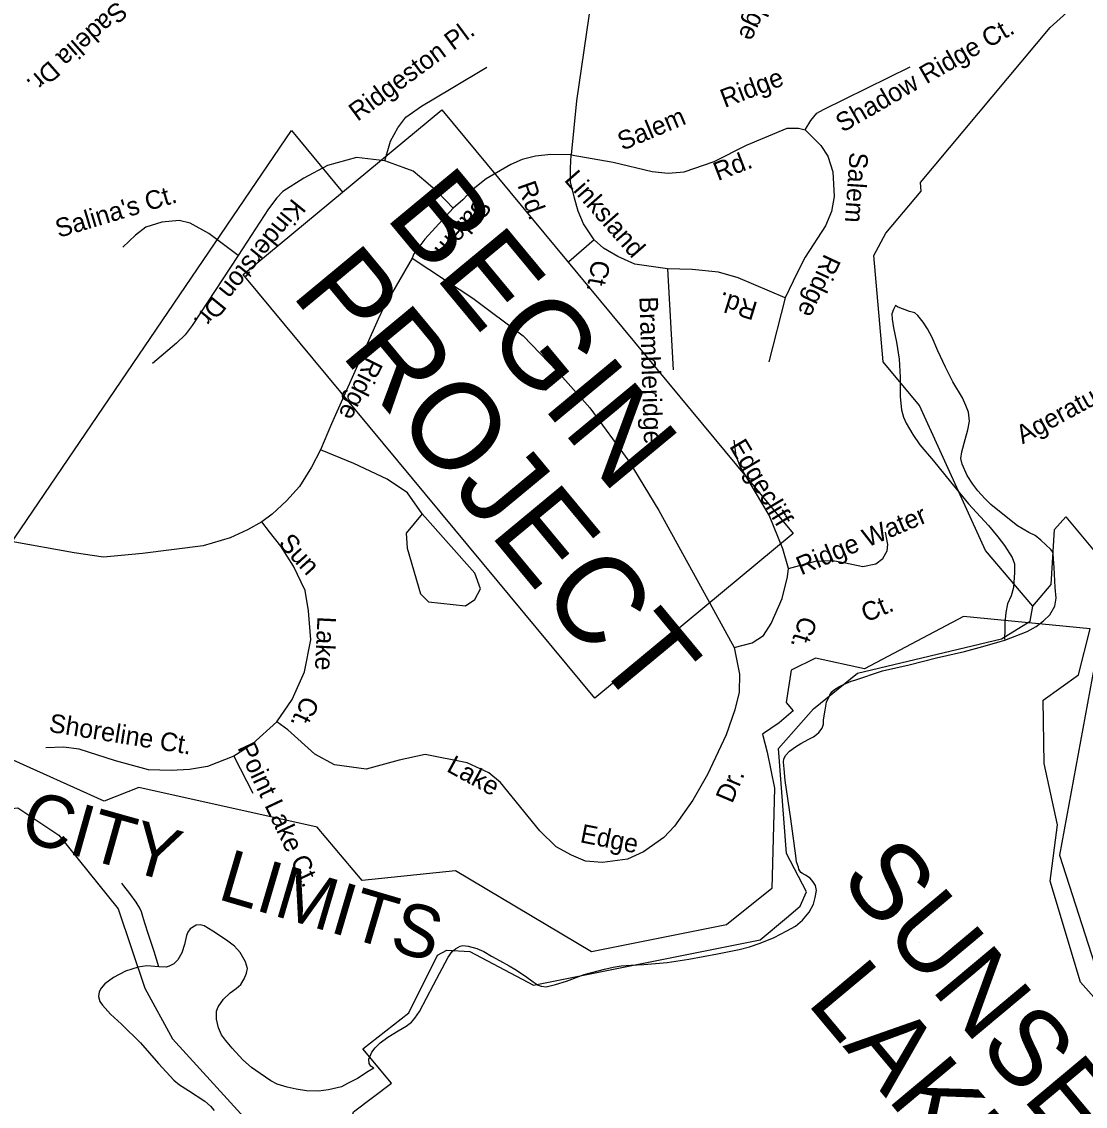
# Model space of a CAD drawing. Extents: x 2054826 to 2060231, y 685508 to 690809.
# Drawn here: x 2058702.3 to 2058824.2, y 689558.4 to 689682.8 of the extents above; entities that cross this region are included whole.
import ezdxf

# ---------------------------------------------------------------- set-up
doc = ezdxf.new("R2010")
doc.units = 0
for name, color, linetype in [('Old_Level_10', 7, 'Continuous'), ('Old_Level_19', 7, 'Continuous'), ('Old_Level_21', 7, 'Continuous'), ('Old_Level_35', 7, 'Continuous'), ('Old_Level_48', 7, 'Continuous'), ('Old_Level_49', 7, 'Continuous'), ('Old_Level_59', 7, 'Continuous'), ('Old_Level_60', 7, 'Continuous'), ('Old_Level_62', 7, 'Continuous'), ('Prop Dimension', 7, 'Continuous'), ('Prop Horizontal Alignment Station Label', 7, 'Continuous')]:
    doc.layers.add(name, color=color, linetype=linetype)

msp = doc.modelspace()

# ---------------------------------------------------------------- linework, layer by layer
at = {"layer": 'Old_Level_21'}
msp.add_line((2058805.24, 689577.2), (2058805.24, 689577.2), dxfattribs=at)
at = {"layer": 'Old_Level_35'}
for p, q in [((2058767.9, 689657.81), (2058765.02, 689655.29)), ((2058776.31, 689654.46), (2058776.97, 689642.9)), ((2058789.8, 689651.16), (2058787.92, 689643.79)), ((2058726.58, 689598.57), (2058728.76, 689594.34))]:
    msp.add_line(p, q, dxfattribs=at)
for points in [[(2058764.19, 689707.99), (2058766.14, 689702.54), (2058767.28, 689698.06), (2058767.69, 689693.65), (2058767.83, 689688.67), (2058767.56, 689685.33), (2058765.89, 689673.74), (2058765.28, 689667.56)], [(2058743.9, 689666.85), (2058744.57, 689669.11), (2058745.38, 689670.64), (2058746.33, 689671.88), (2058748.1, 689673.14), (2058751.52, 689675.15), (2058755.6, 689677.6)], [(2058792.11, 689670.42), (2058792.76, 689671.47), (2058793.46, 689672.33), (2058794.2, 689672.73), (2058804.14, 689677.65)], [(2058765.28, 689667.56), (2058770.07, 689666.7), (2058774.57, 689665.65), (2058776.4, 689665.43), (2058778.24, 689665.61), (2058781.67, 689666.78), (2058785.39, 689668.64), (2058790.03, 689670.6), (2058791.33, 689670.61), (2058792.11, 689670.42)], [(2058792.11, 689670.42), (2058793.9, 689668.63), (2058794.71, 689667.38), (2058795.29, 689665.6), (2058795.41, 689662.75), (2058795.13, 689661.05), (2058794.43, 689659.39), (2058792.1, 689655.8), (2058791.2, 689654.03), (2058789.8, 689651.16)], [(2058743.9, 689666.85), (2058740.66, 689667.25), (2058737.34, 689666.34), (2058734.61, 689664.86), (2058732.2, 689663.35), (2058731.51, 689662.61), (2058730.58, 689661.37), (2058727.07, 689656)], [(2058765.28, 689667.56), (2058762.94, 689667.6), (2058761.19, 689667.38), (2058759.65, 689667), (2058758.36, 689666.43), (2058755.53, 689664.8), (2058753.84, 689663.44), (2058752.85, 689662.39), (2058751.74, 689661.41)], [(2058767.9, 689657.81), (2058766.7, 689659.64), (2058766.06, 689661.09), (2058765.67, 689662.57), (2058765.19, 689664.43), (2058765.18, 689666.01), (2058765.28, 689667.56)], [(2058751.74, 689661.41), (2058749.97, 689663.26), (2058748.62, 689664.46), (2058747.16, 689665.67), (2058746, 689666.11), (2058743.9, 689666.85)], [(2058751.74, 689661.41), (2058748.51, 689657.86), (2058747.25, 689656.18), (2058747.03, 689655.71)], [(2058727.07, 689656), (2058723.73, 689658.51), (2058721.59, 689659.72), (2058720.32, 689660.02), (2058718.33, 689659.82), (2058716.49, 689659.25), (2058715.33, 689658.33), (2058713.87, 689656.94)], [(2058776.31, 689654.46), (2058772.58, 689654.99), (2058770.63, 689655.9), (2058768.98, 689656.85), (2058767.9, 689657.81)], [(2058727.07, 689656), (2058721.83, 689647.97), (2058721.02, 689646.9), (2058720.01, 689645.94), (2058717.25, 689643.63)], [(2058747.03, 689655.71), (2058743.8, 689650.08), (2058743.15, 689648.69), (2058737.8, 689636.68), (2058736.54, 689633.71)], [(2058747.03, 689655.71), (2058750.86, 689653.16), (2058754.01, 689651.1), (2058759.76, 689646.79), (2058763.66, 689642.75), (2058767.41, 689638.53), (2058771.89, 689632.43), (2058775.33, 689626.76), (2058780.11, 689618.07), (2058783.95, 689611.03)], [(2058789.8, 689651.16), (2058784.43, 689653.44), (2058782.15, 689654.08), (2058779.15, 689654.4), (2058776.31, 689654.46)], [(2058790.19, 689620.1), (2058789.56, 689622.35), (2058787.96, 689626.22), (2058785.68, 689630.09), (2058784.64, 689631.82), (2058784.19, 689633.03), (2058783.98, 689634.84)], [(2058736.54, 689633.71), (2058735.49, 689631.74), (2058734.12, 689629.52), (2058732.62, 689627.87), (2058731, 689626.35), (2058729.82, 689625.46)], [(2058748.19, 689626.36), (2058746.5, 689628.78), (2058744.19, 689630.34), (2058740.35, 689632.14), (2058736.54, 689633.71)], [(2058748.19, 689626.36), (2058746.36, 689624.16), (2058746.47, 689622.42), (2058748.01, 689617.2), (2058748.92, 689616.3), (2058753.15, 689615.84), (2058754.21, 689616.56), (2058754.87, 689617.77), (2058754.21, 689619.56), (2058748.19, 689626.36)], [(2058729.82, 689625.46), (2058728.17, 689624.55), (2058726.18, 689623.62), (2058723.07, 689622.72), (2058716.12, 689621.83), (2058711.64, 689621.42), (2058708.29, 689621.9), (2058701.07, 689623.22), (2058698.61, 689623.55), (2058694.9, 689623.44), (2058690.83, 689622.76), (2058682.54, 689620.63)], [(2058731.53, 689602.54), (2058733.27, 689605.08), (2058734.7, 689608.25), (2058735.43, 689611.92), (2058735.17, 689615.27), (2058734.76, 689617.59), (2058733.44, 689620.39), (2058731.98, 689622.68), (2058730.67, 689624.31), (2058729.82, 689625.46)], [(2058790.19, 689620.1), (2058793.29, 689620.94), (2058795.27, 689621.01), (2058796.72, 689620.76), (2058798.72, 689620.33), (2058800.2, 689620.66), (2058801, 689621.27), (2058801.51, 689622.15), (2058801.6, 689622.85), (2058801.33, 689624.26)], [(2058783.95, 689611.03), (2058786.04, 689611.59), (2058787.31, 689612.43), (2058788.21, 689613.8), (2058789.45, 689616.65), (2058790.07, 689619.16), (2058790.19, 689620.1)], [(2058783.95, 689611.03), (2058784.58, 689607.99), (2058784.55, 689605.93), (2058784.03, 689603.91), (2058783.03, 689601.04), (2058780.9, 689596.48), (2058779.23, 689593.53), (2058777.11, 689590.57), (2058775.89, 689589.26), (2058773.58, 689587.62), (2058771.74, 689586.76), (2058768.85, 689586.38), (2058766.9, 689586.56), (2058765.32, 689587.22), (2058763.56, 689588.18), (2058761.66, 689590.04), (2058757.15, 689595.56), (2058755.83, 689596.67), (2058753.34, 689597.81), (2058748.53, 689598.77), (2058745.54, 689598.12), (2058741.75, 689597.1), (2058738.12, 689597.58), (2058735.89, 689598.83), (2058732.77, 689601.6), (2058731.53, 689602.54)], [(2058731.53, 689602.54), (2058728.74, 689599.99), (2058727.62, 689599.22), (2058726.58, 689598.57)], [(2058726.58, 689598.57), (2058723.58, 689597.42), (2058721.51, 689597.05), (2058719.4, 689596.93), (2058716.79, 689597.01), (2058713.02, 689598.05), (2058708.86, 689599.38), (2058707.06, 689599.63), (2058705.04, 689599.53)]]:
    msp.add_lwpolyline(points, dxfattribs=at)
at = {"layer": 'Old_Level_48'}
msp.add_lwpolyline([(2058827.31, 689568.59), (2058823.67, 689572.68), (2058820.19, 689584.27), (2058821.02, 689590.71), (2058819.51, 689597.74), (2058819.41, 689605.02), (2058823.43, 689607.92), (2058824.78, 689613.19), (2058810.24, 689614.6), (2058798.92, 689608.59), (2058793.27, 689609.84), (2058790.51, 689608.46), (2058789.93, 689604.75), (2058790.72, 689603.8), (2058789.14, 689602.41), (2058787.22, 689601.1), (2058787.75, 689599.03), (2058788.58, 689594.91), (2058788.28, 689583.4), (2058783.1, 689579.26), (2058767.61, 689576.16), (2058752.01, 689585.43), (2058741.29, 689584.31), (2058736.15, 689590.46), (2058715.68, 689594.98), (2058711.73, 689593.42), (2058700.51, 689598.47)], dxfattribs=at)
at = {"layer": 'Old_Level_49'}
msp.add_lwpolyline([(2058827.31, 689568.59), (2058823.67, 689572.68), (2058820.19, 689584.27), (2058821.02, 689590.71), (2058819.51, 689597.74), (2058819.41, 689605.02), (2058823.43, 689607.92), (2058824.78, 689613.19), (2058810.24, 689614.6), (2058798.92, 689608.59), (2058793.27, 689609.84), (2058790.51, 689608.46), (2058789.93, 689604.75), (2058790.72, 689603.8), (2058789.14, 689602.41), (2058787.22, 689601.1), (2058787.75, 689599.03), (2058788.58, 689594.91), (2058788.28, 689583.4), (2058783.1, 689579.26), (2058767.61, 689576.16), (2058752.01, 689585.43), (2058741.29, 689584.31), (2058736.15, 689590.46), (2058715.68, 689594.98), (2058711.73, 689593.42), (2058700.51, 689598.47)], dxfattribs=at)
at = {"layer": 'Old_Level_59'}
for points in [[(2058818.2, 689615.77), (2058812.79, 689622.18), (2058805.2, 689638.79), (2058801.04, 689643.8), (2058799.99, 689656.01), (2058801.37, 689658.56), (2058805.42, 689663.38), (2058805.32, 689664.36), (2058820.18, 689682.13), (2058825.15, 689686.66), (2058825.7, 689688.18), (2058840.68, 689694.74), (2058843.75, 689699.42), (2058846.82, 689702.02)], [(2058692.83, 689591.12), (2058695.33, 689590.38), (2058698.93, 689592.37), (2058701.83, 689592.67), (2058706.54, 689589.53), (2058713.31, 689581.09), (2058716.37, 689572), (2058719.54, 689566.18), (2058727.39, 689557.58), (2058734.93, 689553.63)]]:
    msp.add_lwpolyline(points, dxfattribs=at)
at = {"layer": 'Old_Level_60'}
for points in [[(2058739.77, 689555.94), (2058740.33, 689557.81), (2058744.66, 689561.09), (2058741.37, 689565.03), (2058746.66, 689569.16), (2058749.96, 689575.78), (2058751, 689576.33), (2058753.65, 689576.17), (2058760.95, 689572.31), (2058786.96, 689577.54), (2058789.97, 689580.05), (2058791.54, 689581.37), (2058792.27, 689583.02), (2058789.95, 689587.44), (2058789.06, 689599.45), (2058793.04, 689604.01), (2058798.12, 689608.09), (2058814.62, 689612.06), (2058817.91, 689614.08), (2058818.2, 689615.77), (2058820.31, 689618.26), (2058820.69, 689624.59), (2058822, 689626.02), (2058825.64, 689621.66)], [(2058826.88, 689617.73), (2058821.27, 689587.25), (2058825.67, 689573.59)]]:
    msp.add_lwpolyline(points, dxfattribs=at)
at = {"layer": 'Old_Level_62'}
for points in [[(2058802.46, 689650.26), (2058802.24, 689649.82), (2058802.05, 689649.33), (2058802.09, 689648.69), (2058802.23, 689647.7), (2058802.59, 689646.06), (2058802.88, 689644.1), (2058802.98, 689642.05), (2058803.01, 689639.79), (2058803.16, 689638.31), (2058803.36, 689637.45), (2058803.68, 689636.79), (2058804.44, 689635.46), (2058805.26, 689634.29), (2058806.8, 689632.44), (2058808.76, 689630.03), (2058810.85, 689627.54), (2058813.13, 689625.02), (2058814.21, 689623.73), (2058814.96, 689622.75), (2058815.85, 689621.37), (2058816.12, 689620.66), (2058816.11, 689619.64), (2058816.01, 689617.94), (2058815.74, 689616.96), (2058815.29, 689616.07), (2058815.12, 689615.08), (2058815.01, 689613.88), (2058814.99, 689613.01), (2058814.95, 689612.13), (2058814.98, 689611.9)], [(2058820.51, 689621.98), (2058820.26, 689622.27), (2058819.12, 689623.35), (2058818.47, 689623.91), (2058817.76, 689624.25), (2058816.45, 689625.01), (2058815.14, 689626.05), (2058813.38, 689627.44), (2058812.71, 689628.15), (2058811.9, 689629.01), (2058811.33, 689629.79), (2058810.68, 689630.77), (2058810.1, 689632.07), (2058809.97, 689632.72), (2058810.08, 689633.5), (2058810.44, 689634.89), (2058810.76, 689636.02), (2058810.95, 689637.02), (2058810.84, 689638.05), (2058810.54, 689638.81), (2058810.15, 689639.68), (2058809.03, 689641.53), (2058808.21, 689643.21), (2058807.31, 689645.08), (2058806.65, 689646.58), (2058806.14, 689647.59), (2058805.65, 689648.36), (2058805.04, 689649.11), (2058804.69, 689649.42), (2058804.05, 689649.57), (2058803.56, 689649.76), (2058802.94, 689649.99), (2058802.68, 689650.1), (2058802.46, 689650.26)], [(2058814.98, 689611.9), (2058817.55, 689612.88), (2058818.58, 689613.47), (2058819.42, 689614.1), (2058820.17, 689614.81), (2058820.72, 689615.78), (2058820.89, 689616.7), (2058820.77, 689617.94), (2058820.64, 689620.22), (2058820.55, 689621.74), (2058820.51, 689621.98)], [(2058742.66, 689562.8), (2058742.31, 689563.02), (2058742.1, 689563.36), (2058742.06, 689563.84), (2058742.4, 689564.63), (2058742.81, 689565.15), (2058743.37, 689565.7), (2058744.26, 689566.36), (2058745.44, 689567.09), (2058746.35, 689567.61), (2058746.96, 689568.1), (2058747.35, 689568.53), (2058747.88, 689569.31), (2058749.49, 689572.36), (2058751.15, 689575.54), (2058751.62, 689576.19), (2058752.02, 689576.51), (2058752.54, 689576.8), (2058752.84, 689576.87), (2058753.48, 689576.81), (2058754.47, 689576.54), (2058755.26, 689576.2), (2058756.14, 689575.65), (2058757.07, 689575.15), (2058758.16, 689574.55), (2058758.83, 689574.17), (2058760.05, 689573.34), (2058760.91, 689572.7), (2058761.48, 689572.33), (2058761.83, 689572.21), (2058762.39, 689572.15), (2058763.46, 689572.39), (2058764.75, 689572.78), (2058766.75, 689573.53), (2058769.11, 689574.16), (2058770.1, 689574.39), (2058770.99, 689574.55), (2058772.11, 689574.62), (2058773.59, 689574.69), (2058776.28, 689574.91), (2058778.76, 689575.3), (2058782.05, 689575.93), (2058784.53, 689576.41), (2058785.71, 689576.72), (2058786.94, 689577.16), (2058788.53, 689577.81), (2058790.01, 689578.56), (2058790.99, 689579.11), (2058791.78, 689579.79), (2058792.56, 689580.7), (2058793.05, 689581.61), (2058793.26, 689582.38), (2058793.42, 689583.2), (2058793.28, 689583.77), (2058793, 689584.2), (2058792.67, 689584.61), (2058792.14, 689584.93), (2058791.8, 689585.14), (2058791.62, 689585.25), (2058791.38, 689585.63), (2058791.35, 689585.87), (2058791.12, 689586.45), (2058791.05, 689587.15), (2058790.45, 689591.4), (2058789.82, 689595.78), (2058789.71, 689597.14), (2058789.63, 689597.91), (2058789.67, 689598.28), (2058789.89, 689598.72), (2058790.29, 689599.16), (2058790.98, 689599.65), (2058791.61, 689600.02), (2058792.54, 689600.53), (2058793.07, 689600.81), (2058793.42, 689601.09), (2058793.66, 689601.31), (2058794.04, 689601.78), (2058794.21, 689602.27), (2058794.21, 689602.77), (2058794.4, 689603.87), (2058794.56, 689604.78), (2058794.92, 689605.58), (2058795.18, 689605.97), (2058795.47, 689606.22), (2058795.97, 689606.55), (2058796.5, 689606.82), (2058797.36, 689607.2), (2058797.78, 689607.31), (2058800.97, 689608.37), (2058804.03, 689609.07), (2058807.18, 689609.86), (2058810.38, 689610.59), (2058812.47, 689611.15), (2058814.46, 689611.72), (2058814.98, 689611.9)], [(2058717.98, 689574.42), (2058717.44, 689576.17), (2058716.82, 689578.12), (2058716.39, 689579.45), (2058716.17, 689580.2), (2058715.99, 689580.73), (2058715.8, 689581.15), (2058715.4, 689581.83), (2058714.66, 689582.82), (2058713.99, 689583.71), (2058713.73, 689584.02)], [(2058742.66, 689562.8), (2058741.98, 689562.41), (2058740.76, 689561.63), (2058739.64, 689561.04), (2058738.93, 689560.68), (2058737.46, 689560.31), (2058736.29, 689560.18), (2058734.92, 689560.21), (2058733.73, 689560.4), (2058732.69, 689560.62), (2058731.56, 689560.96), (2058730.82, 689561.36), (2058729.61, 689562.19), (2058728.6, 689562.88), (2058727.61, 689563.75), (2058726.39, 689565.11), (2058725.65, 689566), (2058725.18, 689566.64), (2058724.84, 689567.45), (2058724.61, 689568.44), (2058724.59, 689569.36), (2058724.78, 689569.85), (2058725.41, 689570.73), (2058726.16, 689571.45), (2058726.84, 689571.93), (2058727.4, 689572.4), (2058727.77, 689573.07), (2058728.06, 689573.72), (2058728.15, 689574.22), (2058727.91, 689575.02), (2058727.3, 689576.06), (2058726.68, 689576.8), (2058725.76, 689577.48), (2058724.19, 689578.53), (2058723.18, 689579.14), (2058722.74, 689579.26), (2058722.27, 689579.22), (2058721.59, 689578.8), (2058721.31, 689578.42), (2058721.15, 689578.01), (2058720.93, 689576.98), (2058720.62, 689576.03), (2058720.17, 689575.23), (2058719.72, 689574.77), (2058719.19, 689574.49), (2058718.85, 689574.4), (2058717.98, 689574.42)], [(2058717.98, 689574.42), (2058716.6, 689574.54), (2058715.62, 689574.39), (2058714.15, 689573.92), (2058712.8, 689573.21), (2058711.8, 689572.46), (2058711.36, 689571.99), (2058711.14, 689571.55), (2058711.08, 689571.02), (2058711.22, 689570.44), (2058711.55, 689570.04), (2058712.43, 689568.99), (2058713.71, 689567.87), (2058715.89, 689565.7), (2058717.94, 689563.35), (2058719.71, 689561.45), (2058720.36, 689560.88), (2058721.4, 689560.24), (2058723.27, 689559.01), (2058723.92, 689558.45), (2058724.33, 689557.95)]]:
    msp.add_lwpolyline(points, dxfattribs=at)
at = {"layer": 'Prop Dimension'}
for p, q in [((2058727.68, 689653.84), (2058750.44, 689672.71)), ((2058750.44, 689672.71), (2058790.74, 689624.12)), ((2058686.83, 689602.11), (2058733.22, 689670.33)), ((2058733.22, 689670.33), (2058739.06, 689663.28)), ((2058767.98, 689605.24), (2058727.68, 689653.84)), ((2058790.74, 689624.12), (2058767.98, 689605.24))]:
    msp.add_line(p, q, dxfattribs=at)

# ---------------------------------------------------------------- texts
at = {"layer": 'Old_Level_10'}
for s, height, rotation, p in [('Devils Ridge', 2.1325, 245.414, (2058791.07, 689695.76)), ('Sadelia Dr.', 2.1325, 221.3762, (2058713.21, 689685.27)), ('Ridgeston Pl.', 2.1325, 36.5433, (2058740.78, 689671.32)), ('Shadow Ridge Ct.', 2.1325, 30.0457, (2058796.39, 689670.06)), ('Ridge', 2.133, 21.0884, (2058782.88, 689672.91)), ('Salem', 2.133, 22.8101, (2058771.15, 689668)), ('Rd.', 2.133, 21.0884, (2058782.09, 689664.53)), ('Salem', 2.133, 266.0722, (2058797.21, 689667.9)), ('Linksland', 2.133, 311.2874, (2058764.38, 689664.62)), ("Salina's Ct.", 2.1325, 16.7192, (2058706.5, 689658.01)), ('Rd.', 2.133, 289.4808, (2058759.09, 689664.08)), ('Kinderston Dr.', 2.1325, 230.8709, (2058733.34, 689662.65)), ('Salem', 2.133, 229.6188, (2058754.7, 689662.85)), ('Ridge', 2.133, 245.0924, (2058794.33, 689656.29)), ('Ct.', 2.133, 259.8235, (2058767.67, 689655.58)), ('Brambleridge  ', 2.1325, 271.8492, (2058773.09, 689651.26)), ('Rd.', 2.133, 162.9054, (2058786.78, 689650.58)), ('Ridge', 2.133, 243.5543, (2058741.86, 689644.46)), ('Ageratum Ct.', 2.1325, 28.6134, (2058817.03, 689634.33)), ('Edgecliff', 2.133, 300.7754, (2058783.35, 689634.13)), ('Ridge Water', 2.1325, 22.8459, (2058791.64, 689619.31)), ('Sun', 2.133, 312.4067, (2058731.61, 689622.92)), ('Ct.', 2.133, 23.2323, (2058799.09, 689613.89)), ('Lake', 2.133, 267.2304, (2058736.19, 689614.64)), ('Ct.', 2.133, 252.8036, (2058791.49, 689614.77)), ('Ct.', 2.133, 245.3119, (2058734.54, 689605.64)), ('Shoreline Ct.', 2.1325, 350.8226, (2058705.3, 689601.39)), ('Point Lake Ct.', 2.1325, 295.2513, (2058726.96, 689599.56)), ('Lake', 2.133, 331.361, (2058750.87, 689596.91)), ('Dr.', 2.133, 67.0995, (2058783.73, 689593.08)), ('Edge', 2.133, 348.7691, (2058766.2, 689588.73))]:
    msp.add_text(s, height=height, rotation=rotation, dxfattribs=at).set_placement(p)
at = {"layer": 'Old_Level_19'}
for s, rotation, p in [('CITY', 344.2959, (2058701.85, 689589.02)), ('LIMITS', 343.574, (2058724.59, 689582.24))]:
    msp.add_text(s, height=5.998, rotation=rotation, dxfattribs=at).set_placement(p)
at = {"layer": 'Old_Level_21'}
for s, p in [('SUNSET', (2058795.92, 689584.45)), ('LAKE', (2058792.16, 689570.35))]:
    msp.add_text(s, height=8.797, rotation=309.9093, dxfattribs=at).set_placement(p)
at = {"layer": 'Prop Horizontal Alignment Station Label'}
for s, p in [('BEGIN', (2058743.81, 689660.49)), ('PROJECT', (2058733.03, 689651.56))]:
    msp.add_text(s, height=10, rotation=309.6672, dxfattribs=at).set_placement(p)

doc.saveas('drawing.dxf')
